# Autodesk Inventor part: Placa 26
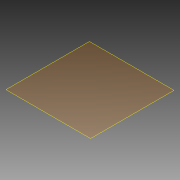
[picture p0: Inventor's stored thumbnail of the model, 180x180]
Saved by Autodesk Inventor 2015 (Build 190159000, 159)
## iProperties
Created: 2015-04
Part Number: Placa 26
Material: Generic
Document SubType Name: Modeling
Designer: suporte
Density: 1 g/cm^3
Appearance: Default
Author: suporte
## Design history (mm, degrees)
workplane "Work Plane1"
sketch "Sketch1"
  geometry: L1 (-840.466, -875)-(-859.534, -875) reference; L2 (-900, -887.5)-(-800, -887.5); L3 (-800, -887.5)-(-800, -875); L4 (-800, -875)-(-900, -875); L5 (-900, -875)-(-900, -887.5); 2 further points
  constraints: 8 end point, 2 midpoint, 2 parallel, 1 horizontal, 1 perpendicular
  dimensions: "d0" = 12.5 distance of L2.end L3.end; "d1" = 100 distance of L2.start L2.end
extrude "Extrusion1" new body sketch "Sketch1" distance "d2" = 2100; taper "d3" = 0 deg
body "Solid1"
node "Reference1"
